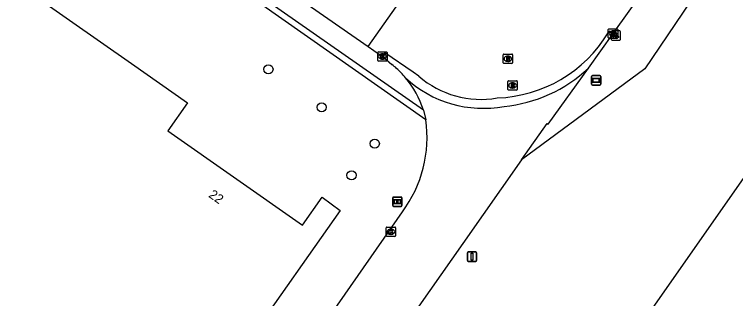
# Model space of a CAD drawing. Extents: x 155018 to 156648, y 383980 to 385733.
# Drawn here: x 155494.6 to 155571.4, y 384675.7 to 384706 of the extents above; entities that cross this region are included whole.
import ezdxf

# ---------------------------------------------------------------- set-up
doc = ezdxf.new("R2010")
doc.units = 0
for name, color, linetype in [('IMGEO_Berm_groen', 7, 'Continuous'), ('IMGEO_Boom', 7, 'Continuous'), ('IMGEO_Informatiebord', 7, 'Continuous'), ('IMGEO_Kolk', 7, 'Continuous'), ('IMGEO_Lichtpunt', 7, 'Continuous'), ('IMGEO_Pand', 7, 'Continuous'), ('IMGEO_Pand_nummerreeks', 7, 'Continuous'), ('IMGEO_Pand_vergunning_verleend', 7, 'Continuous'), ('IMGEO_Rijbaan_lokaal_gesloten', 7, 'Continuous'), ('IMGEO_Rijbaan_lokaal_open', 7, 'Continuous'), ('IMGEO_Rioolput', 7, 'Continuous'), ('IMGEO_Straatnaambord', 7, 'Continuous'), ('IMGEO_Verkeersbordpaal', 7, 'Continuous'), ('IMGEO_Voetpad_open', 7, 'Continuous')]:
    doc.layers.add(name, color=color, linetype=linetype)

msp = doc.modelspace()

# ---------------------------------------------------------------- linework, layer by layer
at = {"layer": 'IMGEO_Berm_groen'}
msp.add_lwpolyline([(155581.396, 384728.861), (155569.829, 384712.251), (155561.724, 384700.24), (155548.597, 384690.515)], dxfattribs=at)
at = {"layer": 'IMGEO_Boom'}
for centre in [(155521.637, 384700.175), (155527.307, 384696.124), (155532.963, 384692.246), (155530.491, 384688.878)]:
    msp.add_circle(centre, 0.489, dxfattribs=at)
at = {"layer": 'IMGEO_Informatiebord'}
for p, q in [((155534.873, 384685.66), (155534.873, 384686.46)), ((155534.873, 384686.46), (155534.873, 384685.66)), ((155534.973, 384686.56), (155535.763, 384686.56)), ((155535.763, 384686.56), (155534.973, 384686.56)), ((155535.863, 384686.46), (155535.863, 384685.66)), ((155535.863, 384685.66), (155535.863, 384686.46)), ((155535.763, 384685.56), (155534.973, 384685.56)), ((155534.973, 384685.56), (155535.763, 384685.56))]:
    msp.add_line(p, q, dxfattribs=at)
for points in [[(155534.974, 384686.292), (155535.762, 384686.292), (155535.762, 384685.828), (155534.974, 384685.828), (155534.974, 384686.292)], [(155535.039, 384686.227), (155535.039, 384685.893), (155535.314, 384685.893), (155535.315, 384686.106), (155535.419, 384686.107), (155535.42, 384685.893), (155535.697, 384685.893), (155535.697, 384686.227), (155535.421, 384686.227), (155535.421, 384686.147), (155535.315, 384686.147), (155535.315, 384686.227), (155535.039, 384686.227)]]:
    msp.add_lwpolyline(points, dxfattribs=at)
for centre, start, end in [((155534.973, 384686.46), 90, 180), ((155534.973, 384686.46), 90, 180), ((155535.763, 384686.46), 0, 90), ((155535.763, 384686.46), 360, 90), ((155534.973, 384685.66), 180, 270), ((155534.973, 384685.66), 180, 270), ((155535.763, 384685.66), 270, 0), ((155535.763, 384685.66), 270, 0)]:
    msp.add_arc(centre, 0.1, start, end, dxfattribs=at)
at = {"layer": 'IMGEO_Kolk'}
for p, q in [((155557.837, 384703.548), (155557.837, 384704.4)), ((155557.912, 384704.474), (155558.764, 384704.474)), ((155558.325, 384704.254), (155558.35, 384704.254)), ((155558.838, 384704.4), (155558.838, 384703.548)), ((155558.764, 384703.474), (155557.912, 384703.474)), ((155558.348, 384703.694), (155558.323, 384703.694)), ((155533.278, 384701.114), (155533.278, 384701.966)), ((155533.353, 384702.04), (155534.205, 384702.04)), ((155533.766, 384701.82), (155533.791, 384701.82)), ((155534.279, 384701.966), (155534.279, 384701.114)), ((155534.205, 384701.04), (155533.353, 384701.04)), ((155533.789, 384701.26), (155533.764, 384701.26)), ((155534.262, 384683.354), (155535.114, 384683.354)), ((155534.187, 384682.428), (155534.187, 384683.28)), ((155534.698, 384682.574), (155534.673, 384682.574)), ((155534.675, 384683.134), (155534.7, 384683.134)), ((155535.188, 384683.28), (155535.188, 384682.428)), ((155535.114, 384682.354), (155534.262, 384682.354))]:
    msp.add_line(p, q, dxfattribs=at)
for points in [[(155557.837, 384703.548), (155557.837, 384704.4)], [(155557.912, 384704.474), (155558.764, 384704.474)], [(155558.158, 384704.174), (155558.281, 384704.174), (155558.281, 384704.023), (155558.411, 384704.174), (155558.575, 384704.174), (155558.429, 384704.023), (155558.582, 384703.774), (155558.43, 384703.774), (155558.345, 384703.938), (155558.281, 384703.871), (155558.281, 384703.774), (155558.158, 384703.774), (155558.158, 384704.174)], [(155558.838, 384704.4), (155558.838, 384703.548)], [(155558.764, 384703.474), (155557.912, 384703.474)], [(155533.278, 384701.114), (155533.278, 384701.966)], [(155533.353, 384702.04), (155534.205, 384702.04)], [(155533.599, 384701.74), (155533.722, 384701.74), (155533.722, 384701.589), (155533.852, 384701.74), (155534.016, 384701.74), (155533.87, 384701.589), (155534.023, 384701.34), (155533.871, 384701.34), (155533.786, 384701.504), (155533.722, 384701.437), (155533.722, 384701.34), (155533.599, 384701.34), (155533.599, 384701.74)], [(155534.279, 384701.966), (155534.279, 384701.114)], [(155534.205, 384701.04), (155533.353, 384701.04)], [(155534.262, 384683.354), (155535.114, 384683.354)], [(155534.187, 384682.428), (155534.187, 384683.28)], [(155534.508, 384683.054), (155534.631, 384683.054), (155534.631, 384682.903), (155534.761, 384683.054), (155534.925, 384683.054), (155534.779, 384682.903), (155534.932, 384682.654), (155534.78, 384682.654), (155534.695, 384682.818), (155534.631, 384682.751), (155534.631, 384682.654), (155534.508, 384682.654), (155534.508, 384683.054)], [(155535.188, 384683.28), (155535.188, 384682.428)], [(155535.114, 384682.354), (155534.262, 384682.354)]]:
    msp.add_lwpolyline(points, dxfattribs=at)
for centre, start, end in [((155557.914, 384704.398), 91.55205, 178.44795), ((155557.914, 384704.398), 91.55205, 178.44795), ((155558.762, 384704.398), 1.55205, 88.44795), ((155558.762, 384704.398), 1.55205, 88.44795), ((155557.914, 384703.55), 181.55205, 268.44795), ((155557.914, 384703.55), 181.55205, 268.44795), ((155558.762, 384703.55), 271.55205, 358.44795), ((155558.762, 384703.55), 271.55205, 358.44795), ((155533.355, 384701.964), 91.55205, 178.44795), ((155533.355, 384701.964), 91.55205, 178.44795), ((155534.203, 384701.964), 1.55205, 88.44795), ((155534.203, 384701.964), 1.55205, 88.44795), ((155533.355, 384701.116), 181.55205, 268.44795), ((155533.355, 384701.116), 181.55205, 268.44795), ((155534.203, 384701.116), 271.55205, 358.44795), ((155534.203, 384701.116), 271.55205, 358.44795), ((155534.264, 384683.278), 91.55205, 178.44795), ((155534.264, 384683.278), 91.55205, 178.44795), ((155535.112, 384683.278), 1.55205, 88.44795), ((155535.112, 384683.278), 1.55205, 88.44795), ((155534.264, 384682.43), 181.55205, 268.44795), ((155534.264, 384682.43), 181.55205, 268.44795), ((155535.112, 384682.43), 271.55205, 358.44795), ((155535.112, 384682.43), 271.55205, 358.44795)]:
    msp.add_arc(centre, 0.0765, start, end, dxfattribs=at)
for centre, major_axis, ratio, start_param, end_param in [((155558.324, 384703.974), (-0.387, 0.002), 0.722429, 4.712389, 7.853982), ((155558.349, 384703.974), (-0.39, 0.002), 0.717154, 1.570796, 4.712389), ((155533.765, 384701.54), (-0.387, 0.002), 0.722429, 4.712389, 7.853982), ((155533.79, 384701.54), (-0.39, 0.002), 0.717154, 1.570796, 4.712389), ((155534.674, 384682.854), (-0.387, 0.002), 0.722429, 4.712389, 7.853982), ((155534.699, 384682.854), (-0.39, 0.002), 0.717154, 1.570796, 4.712389)]:
    msp.add_ellipse(centre, major_axis=major_axis, ratio=ratio, start_param=start_param, end_param=end_param, dxfattribs=at)
at = {"layer": 'IMGEO_Lichtpunt'}
for p, q in [((155558.148, 384704.175), (155558.148, 384703.368)), ((155558.148, 384704.175), (155558.148, 384703.368)), ((155559.05, 384704.27), (155558.242, 384704.27)), ((155559.05, 384704.27), (155558.242, 384704.27)), ((155559.144, 384703.368), (155559.144, 384704.175)), ((155559.144, 384703.368), (155559.144, 384704.175)), ((155558.242, 384703.274), (155559.05, 384703.274)), ((155558.242, 384703.274), (155559.05, 384703.274))]:
    msp.add_line(p, q, dxfattribs=at)
for points in [[(155558.522, 384703.839), (155558.561, 384703.811), (155558.373, 384703.549), (155558.335, 384703.576), (155558.522, 384703.839)], [(155558.624, 384703.791), (155558.671, 384703.791), (155558.671, 384703.469), (155558.624, 384703.469), (155558.624, 384703.791)], [(155558.734, 384703.811), (155558.772, 384703.838), (155558.959, 384703.576), (155558.92, 384703.548), (155558.734, 384703.811)]]:
    msp.add_lwpolyline(points, dxfattribs=at)
msp.add_circle((155558.647, 384703.973), 0.0994, dxfattribs=at)
for centre, start, end in [((155558.242, 384704.175), 90, 180), ((155558.242, 384704.175), 90, 180), ((155559.05, 384704.175), 0, 90), ((155559.05, 384704.175), 0, 90), ((155558.242, 384703.368), 180, 270), ((155558.242, 384703.368), 180, 270), ((155559.05, 384703.368), 270, 0), ((155559.05, 384703.368), 270, 360)]:
    msp.add_arc(centre, 0.0946, start, end, dxfattribs=at)
at = {"layer": 'IMGEO_Pand'}
msp.add_lwpolyline([(155507.034, 384700.802), (155513.027, 384696.585), (155510.933, 384693.608), (155525.252, 384683.547), (155527.355, 384686.543), (155529.295, 384685.136), (155509.887, 384657.557), (155509.713, 384657.656), (155509.592, 384657.74), (155510.087, 384658.43), (155508.712, 384659.375), (155502.555, 384650.626), (155499.538, 384646.298), (155493.137, 384637.258), (155492.533, 384637.678), (155483.853, 384643.696), (155450.041, 384667.498), (155465.861, 384689.98), (155474.741, 384683.75), (155474.761, 384683.779), (155477.86, 384688.169), (155491.253, 384707.189), (155493.499, 384710.324), (155507.034, 384700.802)], dxfattribs=at)
at = {"layer": 'IMGEO_Pand_vergunning_verleend'}
msp.add_lwpolyline([(155520.535, 384608.637), (155533.278, 384626.864), (155530.478, 384628.822), (155581.497, 384701.796), (155584.505, 384699.693), (155597.56, 384718.042), (155608.587, 384710.471), (155610.809, 384713.536), (155623.59, 384704.623), (155645.392, 384735.821), (155696.321, 384700.617), (155686.19, 384686.03), (155681.92, 384688.99), (155664.318, 384671.451), (155567.984, 384575.464), (155520.535, 384608.637)], dxfattribs=at)
at = {"layer": 'IMGEO_Rijbaan_lokaal_gesloten'}
for points in [[(155558.339, 384703.973), (155565.165, 384713.55), (155573.586, 384725.999), (155578.096, 384732.463)], [(155502.025, 384723.953), (155511.334, 384717.433), (155514.931, 384714.931), (155523.214, 384708.948), (155532.257, 384702.606)], [(155532.257, 384702.606), (155536.523, 384708.689)], [(155532.257, 384702.606), (155533.462, 384701.761), (155533.776, 384701.536)], [(155548.597, 384690.515), (155551.313, 384694.387), (155551.447, 384694.314), (155555.717, 384700.295)], [(155538.141, 384695.805), (155538.402, 384694.802)], [(155548.597, 384690.515), (155542.333, 384681.585), (155500, 384621.237), (155495.509, 384614.73)], [(155489.591, 384618.73), (155493.556, 384624.321), (155497.189, 384629.492), (155503.959, 384639.135), (155505.759, 384641.704), (155508.854, 384646.113), (155510.676, 384648.693), (155535.909, 384684.979)]]:
    msp.add_lwpolyline(points, dxfattribs=at)
for centre, radius, start, end in [((155528.415, 384692.743), 10.196, 17.47707, 39.81793), ((155525.238, 384692.915), 13.298, 323.36119, 8.1577)]:
    msp.add_arc(centre, radius, start, end, dxfattribs=at)
at = {"layer": 'IMGEO_Rijbaan_lokaal_open'}
for points in [[(155558.339, 384703.973), (155557.967, 384704.242), (155557.839, 384704.064)], [(155555.717, 384700.295), (155558.339, 384703.973)], [(155537.662, 384699.434), (155537.048, 384699.854), (155534.05, 384701.931), (155533.776, 384701.536)], [(155533.776, 384701.536), (155533.894, 384701.451), (155534.793, 384700.696)]]:
    msp.add_lwpolyline(points, dxfattribs=at)
for centre, radius, start, end in [((155545.505, 384711.54), 14.423, 271.97363, 328.77791), ((155528.397, 384692.707), 10.235, 44.06209, 51.31913), ((155545.315, 384711.301), 15.144, 275.38451, 313.38414), ((155527.991, 384692.353), 10.772, 39.96727, 43.91533), ((155544.246, 384707.004), 10.033, 228.98396, 280.0784), ((155544.496, 384708.087), 12.073, 226.90069, 280.69262)]:
    msp.add_arc(centre, radius, start, end, dxfattribs=at)
at = {"layer": 'IMGEO_Rioolput'}
for p, q in [((155546.717, 384701.793), (155547.569, 384701.793)), ((155546.642, 384700.867), (155546.642, 384701.719)), ((155547.153, 384701.013), (155547.128, 384701.013)), ((155547.13, 384701.573), (155547.155, 384701.573)), ((155547.643, 384701.719), (155547.643, 384700.867)), ((155547.569, 384700.793), (155546.717, 384700.793)), ((155547.141, 384698.029), (155547.141, 384698.881)), ((155547.216, 384698.955), (155548.068, 384698.955)), ((155547.629, 384698.735), (155547.654, 384698.735)), ((155548.142, 384698.881), (155548.142, 384698.029)), ((155548.068, 384697.955), (155547.216, 384697.955)), ((155547.652, 384698.175), (155547.627, 384698.175))]:
    msp.add_line(p, q, dxfattribs=at)
for points in [[(155546.717, 384701.793), (155547.569, 384701.793)], [(155546.642, 384700.867), (155546.642, 384701.719)], [(155547.231, 384701.491), (155546.979, 384701.493), (155546.979, 384701.093)], [(155546.979, 384701.093), (155547.103, 384701.093), (155547.103, 384701.255), (155547.114, 384701.255)], [(155547.157, 384701.412), (155547.103, 384701.412), (155547.103, 384701.331)], [(155547.103, 384701.331), (155547.155, 384701.331)], [(155547.161, 384701.226), (155547.232, 384701.093), (155547.372, 384701.093), (155547.307, 384701.219)], [(155547.643, 384701.719), (155547.643, 384700.867)], [(155547.569, 384700.793), (155546.717, 384700.793)], [(155547.141, 384698.029), (155547.141, 384698.881)], [(155547.216, 384698.955), (155548.068, 384698.955)], [(155547.73, 384698.653), (155547.478, 384698.655), (155547.478, 384698.255)], [(155548.142, 384698.881), (155548.142, 384698.029)], [(155548.068, 384697.955), (155547.216, 384697.955)], [(155547.478, 384698.255), (155547.602, 384698.255), (155547.602, 384698.417), (155547.613, 384698.417)], [(155547.656, 384698.574), (155547.602, 384698.574), (155547.602, 384698.493)], [(155547.602, 384698.493), (155547.654, 384698.493)], [(155547.66, 384698.388), (155547.731, 384698.255), (155547.871, 384698.255), (155547.806, 384698.381)]]:
    msp.add_lwpolyline(points, dxfattribs=at)
for centre, radius, start, end in [((155546.719, 384701.717), 0.0765, 91.55205, 178.44795), ((155546.719, 384701.717), 0.0765, 91.55205, 178.44795), ((155547.567, 384701.717), 0.0765, 1.55205, 88.44795), ((155547.567, 384701.717), 0.0765, 1.55205, 88.44795), ((155547.113, 384701.202), 0.0533, 26.02933, 88.69889), ((155547.139, 384701.52), 0.19, 274.7715, 282.96867), ((155547.163, 384701.316), 0.0964, 77.00612, 93.18647), ((155547.177, 384701.373), 0.0378, 276.66336, 79.67722), ((155547.23, 384701.381), 0.109, 350.36119, 89.41601), ((155547.228, 384701.381), 0.112, 277.58423, 350.98172), ((155547.212, 384701.166), 0.108, 29.51342, 73.79051), ((155546.719, 384700.869), 0.0765, 181.55205, 268.44795), ((155546.719, 384700.869), 0.0765, 181.55205, 268.44795), ((155547.567, 384700.869), 0.0765, 271.55205, 358.44795), ((155547.567, 384700.869), 0.0765, 271.55205, 358.44795), ((155547.218, 384698.879), 0.0765, 91.55205, 178.44795), ((155547.218, 384698.879), 0.0765, 91.55205, 178.44795), ((155547.729, 384698.543), 0.109, 350.36119, 89.41601), ((155548.066, 384698.879), 0.0765, 1.55205, 88.44795), ((155548.066, 384698.879), 0.0765, 1.55205, 88.44795), ((155547.218, 384698.031), 0.0765, 181.55205, 268.44795), ((155547.218, 384698.031), 0.0765, 181.55205, 268.44795), ((155547.612, 384698.364), 0.0533, 26.02933, 88.69889), ((155547.638, 384698.682), 0.19, 274.7715, 282.96867), ((155547.662, 384698.478), 0.0964, 77.00612, 93.18647), ((155547.676, 384698.535), 0.0378, 276.66336, 79.67722), ((155547.727, 384698.543), 0.112, 277.58423, 350.98172), ((155547.711, 384698.328), 0.108, 29.51342, 73.79051), ((155548.066, 384698.031), 0.0765, 271.55205, 358.44795), ((155548.066, 384698.031), 0.0765, 271.55205, 358.44795)]:
    msp.add_arc(centre, radius, start, end, dxfattribs=at)
for centre, major_axis, ratio, start_param, end_param in [((155547.129, 384701.293), (-0.387, 0.002), 0.722429, 4.712389, 7.853982), ((155547.154, 384701.293), (-0.39, 0.002), 0.717154, 1.570796, 4.712389), ((155547.628, 384698.455), (-0.387, 0.002), 0.722429, 4.712389, 7.853982), ((155547.653, 384698.455), (-0.39, 0.002), 0.717154, 1.570796, 4.712389)]:
    msp.add_ellipse(centre, major_axis=major_axis, ratio=ratio, start_param=start_param, end_param=end_param, dxfattribs=at)
at = {"layer": 'IMGEO_Straatnaambord'}
for p, q in [((155556.142, 384699.496), (155556.932, 384699.496)), ((155556.932, 384699.496), (155556.142, 384699.496)), ((155556.042, 384698.596), (155556.042, 384699.396)), ((155556.042, 384699.396), (155556.042, 384698.596)), ((155557.032, 384699.396), (155557.032, 384698.596)), ((155557.032, 384698.596), (155557.032, 384699.396)), ((155556.932, 384698.496), (155556.142, 384698.496)), ((155556.142, 384698.496), (155556.932, 384698.496))]:
    msp.add_line(p, q, dxfattribs=at)
for points in [[(155556.143, 384699.228), (155556.931, 384699.228), (155556.931, 384698.764), (155556.143, 384698.764), (155556.143, 384699.228)], [(155556.208, 384699.163), (155556.208, 384698.829), (155556.866, 384698.829), (155556.866, 384699.163), (155556.208, 384699.163)]]:
    msp.add_lwpolyline(points, dxfattribs=at)
for centre, start, end in [((155556.142, 384699.396), 90, 180), ((155556.142, 384699.396), 90, 180), ((155556.932, 384699.396), 0, 90), ((155556.932, 384699.396), 360, 90), ((155556.142, 384698.596), 180, 270), ((155556.142, 384698.596), 180, 270), ((155556.932, 384698.596), 270, 0), ((155556.932, 384698.596), 270, 0)]:
    msp.add_arc(centre, 0.1, start, end, dxfattribs=at)
at = {"layer": 'IMGEO_Verkeersbordpaal'}
for p, q in [((155542.826, 384679.797), (155542.826, 384680.597)), ((155542.826, 384680.597), (155542.826, 384679.797)), ((155542.926, 384680.697), (155543.716, 384680.697)), ((155543.716, 384680.697), (155542.926, 384680.697)), ((155543.816, 384680.597), (155543.816, 384679.797)), ((155543.816, 384679.797), (155543.816, 384680.597)), ((155543.716, 384679.697), (155542.926, 384679.697)), ((155542.926, 384679.697), (155543.716, 384679.697))]:
    msp.add_line(p, q, dxfattribs=at)
msp.add_lwpolyline([(155543.246, 384680.572), (155543.396, 384680.572), (155543.396, 384679.822), (155543.246, 384679.822), (155543.246, 384680.572)], dxfattribs=at)
for centre, start, end in [((155542.926, 384680.597), 90, 180), ((155542.926, 384680.597), 90, 180), ((155543.716, 384680.597), 0, 90), ((155543.716, 384680.597), 360, 90), ((155542.926, 384679.797), 180, 270), ((155542.926, 384679.797), 180, 270), ((155543.716, 384679.797), 270, 0), ((155543.716, 384679.797), 270, 0)]:
    msp.add_arc(centre, 0.1, start, end, dxfattribs=at)
at = {"layer": 'IMGEO_Voetpad_open'}
for points in [[(155538.141, 384695.805), (155501.024, 384721.806)], [(155538.402, 384694.802), (155500.225, 384721.622)]]:
    msp.add_lwpolyline(points, dxfattribs=at)

# ---------------------------------------------------------------- texts
at = {"layer": 'IMGEO_Pand_nummerreeks'}
msp.add_text('22', height=1, rotation=324.90634, dxfattribs=at).set_placement((155515.188, 384686.61))

doc.saveas('drawing.dxf')
